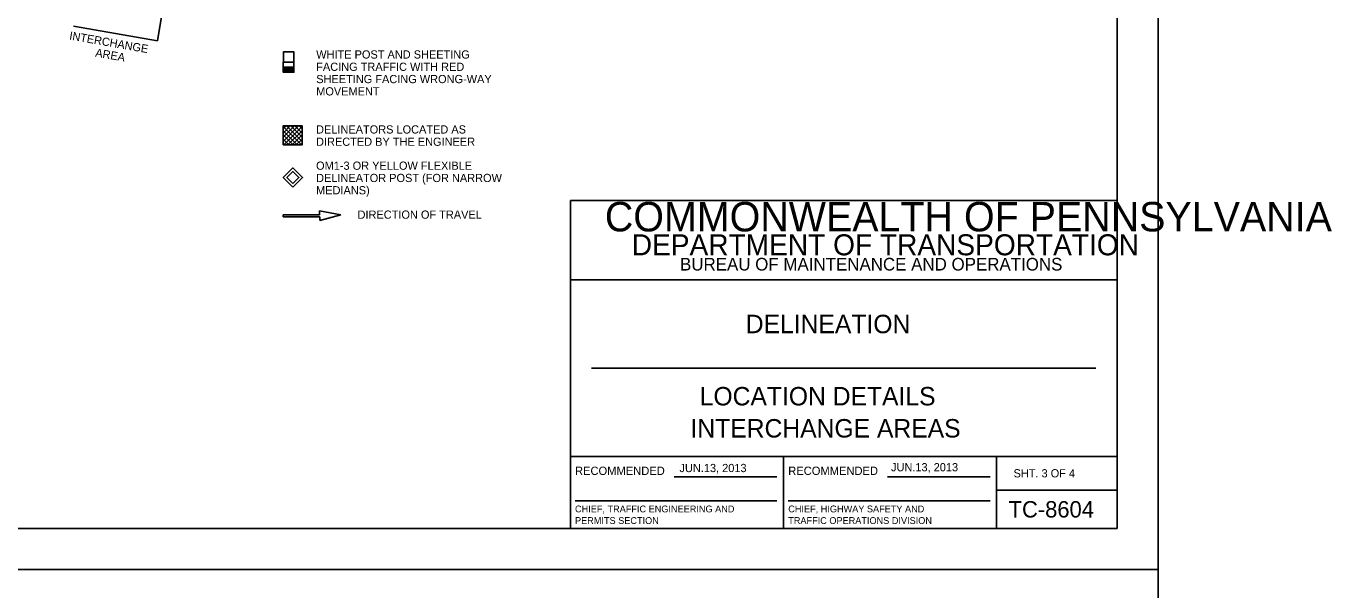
# Model space of a CAD drawing. Extents: x 640253 to 641999, y 298458 to 299646.
# Drawn here: x 641521.2 to 641998.9, y 299044.1 to 299250.5 of the extents above; entities that cross this region are included whole.
import ezdxf

# ---------------------------------------------------------------- set-up
doc = ezdxf.new("R2010")
doc.units = 0
for name, color, linetype in [('1', 7, 'Continuous'), ('2', 7, 'Continuous'), ('Level 1', 7, 'Continuous'), ('PLT-BNDY', 7, 'Continuous')]:
    doc.layers.add(name, color=color, linetype=linetype)

msp = doc.modelspace()

# ---------------------------------------------------------------- linework, layer by layer
at = {"layer": '1'}
for p, q in [((641920.31, 299066.63), (641920.31, 299630.63)), ((641720.31, 299066.63), (641720.31, 299186.63)), ((641720.31, 299186.63), (641920.31, 299186.63)), ((641920.31, 299157.63), (641720.31, 299157.63)), ((641728.06, 299125.31), (641912.56, 299125.31)), ((641720.31, 299093), (641920.31, 299093)), ((641798.31, 299093), (641798.31, 299066.63)), ((641876.19, 299066.63), (641876.19, 299093)), ((641758.24, 299085.57), (641795.87, 299085.57)), ((641836.24, 299085.57), (641873.87, 299085.57)), ((641876.19, 299080.63), (641920.31, 299080.63)), ((641920.31, 299066.63), (641134.31, 299066.63)), ((641134.31, 299066.63), (641720.31, 299066.63))]:
    msp.add_line(p, q, dxfattribs=at)
at = {"layer": '2'}
for p, q in [((641569.2, 299245.13), (641570.76, 299254.06)), ((641538.53, 299250.5), (641569.2, 299245.13)), ((641615.22, 299213.97), (641622.16, 299213.97)), ((641615.22, 299207.03), (641615.22, 299213.97)), ((641622.16, 299213.97), (641622.16, 299213.97)), ((641622.16, 299207.03), (641622.16, 299213.97)), ((641622.16, 299212.98), (641622.16, 299212.98)), ((641622.16, 299211.99), (641622.16, 299211.99)), ((641622.16, 299211), (641622.16, 299211)), ((641622.16, 299210), (641622.16, 299210)), ((641615.22, 299207.03), (641615.22, 299207.03)), ((641615.22, 299207.03), (641615.22, 299207.03)), ((641615.22, 299207.03), (641615.22, 299207.03)), ((641615.22, 299207.03), (641615.22, 299207.03)), ((641615.22, 299207.03), (641615.22, 299207.03)), ((641615.22, 299207.03), (641615.22, 299207.03)), ((641615.22, 299207.03), (641615.22, 299207.03)), ((641615.22, 299207.03), (641615.22, 299207.03)), ((641615.22, 299207.03), (641615.22, 299207.03)), ((641615.22, 299207.03), (641622.16, 299207.03)), ((641616.21, 299207.03), (641616.21, 299207.03)), ((641617.2, 299207.03), (641617.2, 299207.03)), ((641618.19, 299207.03), (641618.19, 299207.03)), ((641619.2, 299207.03), (641619.2, 299207.03)), ((641620.19, 299207.03), (641620.19, 299207.03)), ((641621.17, 299207.03), (641621.17, 299207.03)), ((641622.16, 299209.01), (641622.16, 299209.01)), ((641622.16, 299208.02), (641622.16, 299208.02)), ((641622.16, 299207.03), (641622.16, 299207.03)), ((641622.16, 299207.03), (641622.16, 299207.03)), ((641628.53, 299181.44), (641615.28, 299181.44)), ((641615.28, 299181.44), (641615.28, 299180.73)), ((641636.33, 299181.41), (641628.53, 299182.88)), ((641628.53, 299182.88), (641628.53, 299181.44)), ((641628.61, 299179.29), (641636.33, 299181.41)), ((641615.28, 299180.73), (641628.61, 299180.73)), ((641628.61, 299180.73), (641628.61, 299179.29))]:
    msp.add_line(p, q, dxfattribs=at)
for points in [[(641615.29, 299237.34), (641619.18, 299237.34), (641619.18, 299241.09), (641615.29, 299241.09)], [(641615.22, 299207.03), (641615.22, 299213.97), (641622.16, 299213.97), (641622.16, 299207.03)], [(641615.22, 299207.03), (641615.22, 299213.97), (641622.16, 299213.97), (641622.16, 299207.03)], [(641618.8, 299191.54), (641615.28, 299195.04), (641618.8, 299198.62), (641622.32, 299195.04)], [(641618.8, 299192.85), (641616.6, 299195.06), (641618.8, 299197.26), (641621.01, 299195.06)]]:
    msp.add_lwpolyline(points, close=True, dxfattribs=at)
for points in [[(641615.26, 299235.48), (641619.16, 299235.48), (641619.16, 299237.36), (641615.26, 299237.36), (641615.26, 299233.61), (641619.16, 299233.61), (641619.16, 299235.4), (641615.33, 299235.4), (641615.33, 299233.67), (641619.09, 299233.67), (641619.09, 299235.33), (641615.41, 299235.33), (641615.41, 299233.73), (641619.01, 299233.73), (641619.01, 299235.26), (641615.48, 299235.26), (641615.48, 299233.81), (641618.93, 299233.81), (641618.93, 299235.18), (641615.55, 299235.18), (641615.55, 299233.89), (641618.84, 299233.89), (641618.84, 299235.1), (641615.63, 299235.1), (641615.63, 299233.97), (641618.75, 299233.97), (641618.75, 299235.01), (641615.72, 299235.01), (641615.72, 299234.04), (641618.67, 299234.04), (641618.67, 299234.93), (641615.81, 299234.93), (641615.81, 299234.14), (641618.57, 299234.14), (641618.56, 299234.83), (641615.9, 299234.83), (641615.9, 299234.23), (641618.45, 299234.23), (641618.45, 299234.74), (641616, 299234.74), (641616, 299234.33), (641618.34, 299234.33), (641618.34, 299234.62), (641616.11, 299234.62), (641616.11, 299234.43), (641618.23, 299234.43), (641618.23, 299234.52), (641616.19, 299234.53)], [(641615.22, 299208.33), (641620.86, 299213.97)], [(641615.22, 299209.86), (641619.34, 299213.97)], [(641615.22, 299211.37), (641617.82, 299213.97)], [(641615.22, 299212.89), (641616.3, 299213.97)], [(641621.92, 299207.03), (641615.22, 299213.73)], [(641620.39, 299207.03), (641615.22, 299212.2)], [(641618.89, 299207.03), (641615.22, 299210.69)], [(641615.45, 299207.03), (641622.16, 299213.74)], [(641622.16, 299208.29), (641616.49, 299213.97)], [(641616.96, 299207.03), (641622.16, 299212.23)], [(641622.16, 299209.82), (641618.02, 299213.97)], [(641618.49, 299207.03), (641622.16, 299210.71)], [(641622.16, 299211.35), (641619.54, 299213.97)], [(641622.16, 299212.86), (641621.05, 299213.97)], [(641617.36, 299207.03), (641615.22, 299209.16)], [(641615.83, 299207.03), (641615.22, 299207.63)], [(641620.01, 299207.03), (641622.16, 299209.18)], [(641621.52, 299207.03), (641622.15, 299207.65)]]:
    msp.add_lwpolyline(points, dxfattribs=at)
at = {"layer": 'Level 1'}
for p, q in [((641721.99, 299076.68), (641795.87, 299076.68)), ((641799.99, 299076.68), (641873.87, 299076.68))]:
    msp.add_line(p, q, dxfattribs=at)
at = {"layer": 'PLT-BNDY'}
for points in [[(641094.31, 299645.63), (641935.31, 299645.63), (641935.31, 299051.63), (641094.31, 299051.63)], [(641094.31, 299051.63), (641935.31, 299051.63), (641935.31, 298457.63), (641094.31, 298457.63)]]:
    msp.add_lwpolyline(points, close=True, dxfattribs=at)

# ---------------------------------------------------------------- texts
at = {"layer": '1'}
for s, height, p in [('COMMONWEALTH OF PENNSYLVANIA', 10.7828, (641732.9, 299175.36)), ('DEPARTMENT OF TRANSPORTATION', 7.6837, (641742.76, 299166.61)), ('BUREAU OF MAINTENANCE AND OPERATIONS', 4.6253, (641760.41, 299161.04)), ('DELINEATION', 6.75, (641784.46, 299138.1)), ('LOCATION DETAILS', 6.75, (641767.61, 299111.66)), ('INTERCHANGE AREAS', 6.75, (641764.24, 299099.91)), ('JUN.13, 2013', 3, (641837.59, 299087.54)), ('RECOMMENDED', 3.048, (641721.99, 299086.2)), ('JUN.13, 2013', 3, (641760.21, 299087.25)), ('RECOMMENDED', 3.048, (641799.99, 299086.2)), ('SHT. 3 OF 4', 3, (641882.4, 299085.31)), ('TC-8604', 6, (641880.6, 299070.63))]:
    msp.add_text(s, height=height, dxfattribs=at).set_placement(p)
at = {"layer": '2'}
for s, p in [('INTERCHANGE', (641536.84, 299245.63)), ('AREA', (641546.35, 299239.4))]:
    msp.add_text(s, height=3, rotation=350.0808, dxfattribs=at).set_placement(p)
for s, p in [('WHITE POST AND SHEETING', (641627.32, 299238.63)), ('FACING TRAFFIC WITH RED ', (641627.32, 299234.13)), ('SHEETING FACING WRONG-WAY', (641627.32, 299229.63)), ('MOVEMENT', (641627.32, 299225.13)), ('DELINEATORS LOCATED AS', (641627.26, 299211.19)), ('DIRECTED BY THE ENGINEER', (641627.26, 299206.69)), ('OM1-3 OR YELLOW FLEXIBLE', (641627.27, 299197.92)), ('DELINEATOR POST (FOR NARROW', (641627.27, 299193.42)), ('MEDIANS)', (641627.27, 299188.92)), ('DIRECTION OF TRAVEL', (641642.44, 299180))]:
    msp.add_text(s, height=3, dxfattribs=at).set_placement(p)
at = {"layer": 'Level 1'}
for s, p in [('CHIEF, TRAFFIC ENGINEERING AND', (641721.99, 299072.51)), ('CHIEF, HIGHWAY SAFETY AND', (641799.99, 299072.51)), ('PERMITS SECTION', (641721.99, 299068.26)), ('TRAFFIC OPERATIONS DIVISION', (641799.99, 299068.26))]:
    msp.add_text(s, height=2.5, dxfattribs=at).set_placement(p)

doc.saveas('drawing.dxf')
